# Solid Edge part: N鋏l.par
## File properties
Author: Türk
Template: Iso Part.par
Last saved by: Türk
Revision: 9
Application: Solid Edge
Accuracy: 0,990
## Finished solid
Body 1: solid body, 3 faces, 2 edges, 0 vertices.
  Faces by surface: plane 2, cylinder 1
  Edges by curve: circle 2
Bounding box of the edges (mm): 7.000 x 39.500 x 7.000, from (-3.5, 0, -3.5) to (3.5, 39.5, 3.5).
Cylindrical faces by radius (mm): R3.5 x1
Planar faces by outward normal: +y 1, -y 1
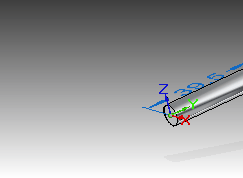
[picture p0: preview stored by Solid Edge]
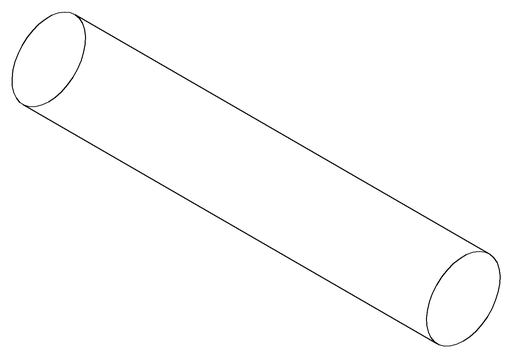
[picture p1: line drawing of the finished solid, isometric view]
